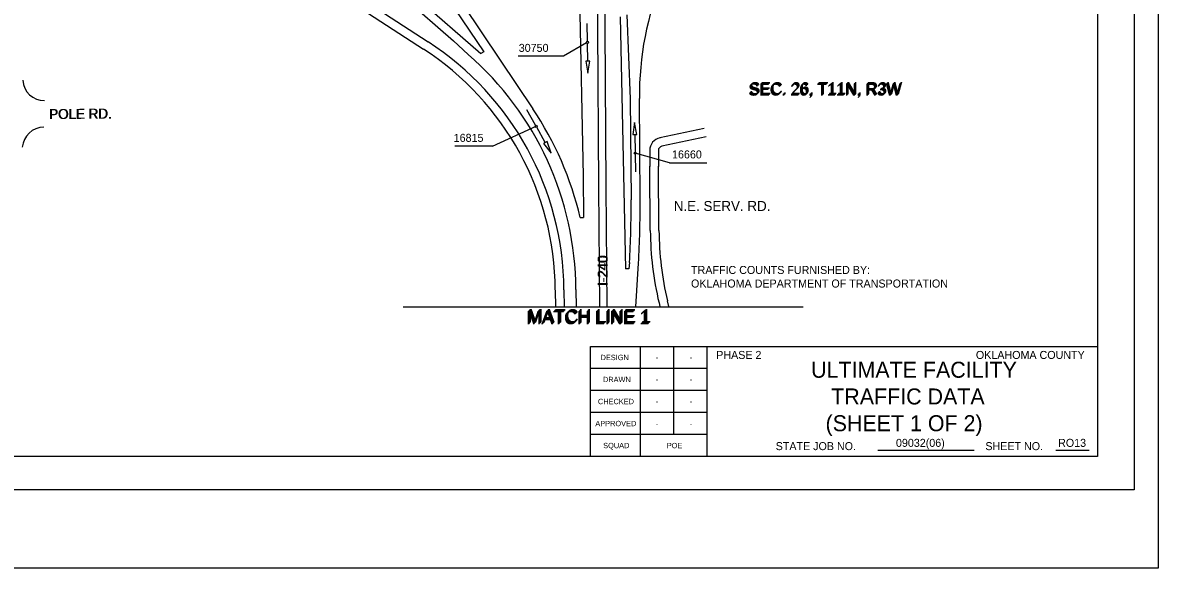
# Model space of a CAD drawing. Extents: x 137200 to 144400, y -2153713 to -2148447.
# Drawn here: x 140995 to 144400, y -2153247 to -2151611 of the extents above; entities that cross this region are included whole.
import ezdxf

# ---------------------------------------------------------------- set-up
doc = ezdxf.new("R2010")
doc.units = 0
for name, color, linetype in [('5', 7, 'Continuous'), ('6', 7, 'Continuous'), ('BASELINE', 7, 'Continuous'), ('EXIST', 7, 'Continuous'), ('PROP', 7, 'Continuous'), ('SHT_Plot_Shape_Full', 7, 'Continuous'), ('SHT_Plot_Shape_Half', 7, 'Continuous'), ('SHT_Sheet_Border', 7, 'Continuous'), ('SHT_Standard_Sheet_Lines', 7, 'Continuous'), ('SHT_Standard_Sheet_Txt', 7, 'Continuous'), ('T', 7, 'Continuous')]:
    doc.layers.add(name, color=color, linetype=linetype)

# ---------------------------------------------------------------- blocks, each defined once
blk = doc.blocks.new('ARR')
at = {"layer": '6'}
for p, q in [((134.5, 0), (0, 0)), ((285.8, 0), (151.3, 0))]:
    blk.add_line(p, q, dxfattribs=at)
blk.add_lwpolyline([(285.8, 15.2), (285.8, -15.2), (377.2, 0)], close=True, dxfattribs=at)
blk.add_circle((142.9, 0), 8.42, dxfattribs=at)

msp = doc.modelspace()

# ---------------------------------------------------------------- linework, layer by layer
at = {"layer": '6'}
for p, q in [((142685.6, -2151671.7), (142616.2, -2151711.8)), ((142616.2, -2151711.8), (142480.4, -2151711.8)), ((142403.7, -2151981.5), (142534.6, -2151921.7)), ((142538.9, -2151900.8), (142538.9, -2151900.8)), ((142403.7, -2151981.5), (142290.5, -2151981.5)), ((142934.2, -2152031.1), (142831.6, -2152002.6)), ((142934.2, -2152031.1), (143046.3, -2152031.1))]:
    msp.add_line(p, q, dxfattribs=at)
at = {"layer": 'BASELINE'}
msp.add_line((142135.5, -2152463.5), (143335.5, -2152463.5), dxfattribs=at)
at = {"layer": 'EXIST'}
for p, q in [((142592.1, -2152413), (142592.5, -2152464.5)), ((142618.1, -2152412.4), (142618.5, -2152464.3))]:
    msp.add_line(p, q, dxfattribs=at)
at = {"layer": 'PROP'}
for p, q in [((142712.7, -2150825), (142718.5, -2151627.2)), ((142734.7, -2150824.8), (142740.5, -2151627)), ((141506.8, -2151241.9), (142196.9, -2151690.4)), ((141520.9, -2151220.1), (142211.1, -2151668.6)), ((142658.1, -2151252.9), (142675.7, -2152071.4)), ((141903.1, -2151296.6), (142368.3, -2151703.3)), ((142023.6, -2151435.2), (142287.2, -2151665.6)), ((142292, -2151571.9), (142377.4, -2151698.9)), ((142314.4, -2151556.9), (142426.6, -2151723.5)), ((142786.2, -2151593.5), (142802.5, -2152349.5)), ((142806.2, -2151587.9), (142817, -2151839.2)), ((142718.5, -2151627.2), (142721.9, -2152103.4)), ((142740.5, -2151627), (142743.9, -2152103.2)), ((142287.2, -2151665.6), (142331.1, -2151706.6)), ((142287.2, -2151665.6), (142331.1, -2151706.6)), ((142377.4, -2151698.9), (142368.3, -2151703.3)), ((142426.6, -2151723.5), (142524.6, -2151869.1)), ((142817, -2151839.2), (142819.2, -2152142.7)), ((142846.2, -2152142.5), (142844, -2151839)), ((142876.8, -2152234.5), (142875.4, -2152041.5)), ((142902.8, -2152234.3), (142901.4, -2152041)), ((142675.7, -2152071.4), (142676.5, -2152195.2)), ((142675.7, -2152071.4), (142676.5, -2152195.2)), ((142721.9, -2152103.4), (142724.5, -2152463.5)), ((142743.9, -2152103.2), (142746.5, -2152463.4)), ((142666.5, -2152195.3), (142676.5, -2152195.2)), ((142666.5, -2152195.3), (142676.5, -2152195.2)), ((142814.3, -2152330.3), (142812.5, -2152349.4)), ((142833.6, -2152462.8), (142841.3, -2152331.9)), ((142812.5, -2152349.4), (142802.5, -2152349.5)), ((142654.1, -2152411.3), (142654.5, -2152464)), ((142903, -2152451.1), (142905.6, -2152462.3)), ((142932.3, -2152462.1), (142928.3, -2152445.1))]:
    msp.add_line(p, q, dxfattribs=at)
for points in [[(143038.7, -2151928.1), (142905.9, -2151956.2)], [(143044, -2151953.6), (142911.3, -2151981.7)], [(142901.1, -2151994.3), (142901.5, -2152042)], [(142875.1, -2151994.5), (142875.5, -2152042.2)]]:
    msp.add_lwpolyline(points, dxfattribs=at)
for centre, radius, start, end in [((143790.9, -2151832.2), 946.9, 90.3443, 180.4098), ((141723.6, -2152418.6), 894.5, 0.4098, 56.9808), ((141723.6, -2152418.6), 868.5, 0.4098, 56.9808), ((141709.2, -2152418), 944.9, 0.4098, 48.8404), ((141709.2, -2152418), 944.9, 0.4098, 48.8404), ((141060.2, -2151779.7), 65, 183.6752, 270.4098), ((141709.2, -2152418), 982.9, 13.0971, 33.9499), ((141709.2, -2152418), 982.9, 13.0971, 33.9499), ((141059, -2151989.7), 65, 90.4098, 175.7019), ((142914, -2151994.2), 38.8, 101.9396, 180.4098), ((142914, -2151994.2), 12.8, 101.9396, 180.4098), ((139973.5, -2152163), 2845.8, 356.6303, 0.4098), ((139973.5, -2152163), 2872.8, 356.6303, 0.4098), ((143844.7, -2152227.6), 967.9, 180.4098, 193.35), ((143844.7, -2152227.6), 941.9, 180.4098, 193.35)]:
    msp.add_arc(centre, radius, start, end, dxfattribs=at)
at = {"layer": 'SHT_Plot_Shape_Full'}
msp.add_lwpolyline([(137199.8, -2148447.1), (144399.8, -2148447.1), (144399.8, -2153247.1), (137199.8, -2153247.1)], close=True, dxfattribs=at)
at = {"layer": 'SHT_Plot_Shape_Half'}
msp.add_lwpolyline([(137527.3, -2148612.1), (144327.3, -2148612.1), (144327.3, -2153012.1), (137527.3, -2153012.1)], close=True, dxfattribs=at)
at = {"layer": 'SHT_Sheet_Border'}
for p, q in [((142697.3, -2152582.1), (144217.3, -2152582)), ((142697.3, -2152912.1), (142697.3, -2152582.1)), ((143047.3, -2152912.1), (143047.3, -2152581.9))]:
    msp.add_line(p, q, dxfattribs=at)
msp.add_lwpolyline([(144217.3, -2152912.1), (137917.3, -2152912.1), (137917.3, -2148712.1), (144217.3, -2148712.1)], close=True, dxfattribs=at)
at = {"layer": 'SHT_Standard_Sheet_Lines'}
for p, q in [((142847.3, -2152912.1), (142847.3, -2152581.9)), ((142947.3, -2152846), (142947.3, -2152581.9)), ((143559.5, -2152892.8), (143847.5, -2152892.8)), ((144092.4, -2152892.8), (144192.9, -2152892.8))]:
    msp.add_line(p, q, dxfattribs=at)
for points in [[(143047.3, -2152648.1), (142697.3, -2152648.1)], [(143047.3, -2152714.1), (142697.3, -2152714.1)], [(143047.3, -2152780.1), (142697.3, -2152780.1)], [(143047.3, -2152846.1), (142697.3, -2152846.1)]]:
    msp.add_lwpolyline(points, dxfattribs=at)

# ---------------------------------------------------------------- block references
at = {"layer": '6'}
for p, xscale, yscale, rotation in [((142687.7, -2151613.8), 0.3937, 0.39370000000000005, -89.1979575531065), ((142507.2, -2151872.6), 0.3937000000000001, 0.39370000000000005, -60.78130935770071), ((142832.9, -2152058.8), 0.39370000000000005, 0.3937, 91.28919224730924)]:
    msp.add_blockref('ARR', p, dxfattribs=dict(at, xscale=xscale, yscale=yscale, rotation=rotation))

# ---------------------------------------------------------------- texts
at = {"layer": '5'}
for s, height, p in [('SEC. 26, T11N, R3W', 36, (143175, -2151825.4)), ('SEC. 26, T11N, R3W', 36, (143170.3, -2151830.1)), ('SEC. 26, T11N, R3W', 36, (143171.9, -2151828.5)), ('SEC. 26, T11N, R3W', 36, (143173.5, -2151826.9)), ('N.E. SERV. RD.', 30, (142947.2, -2152175.8))]:
    msp.add_text(s, height=height, dxfattribs=at).set_placement(p)
for s, rotation, p in [('POLE RD.', 0.5333, (141074, -2151900.4)), ('POLE RD.', 0.5333, (141076, -2151900.4)), ('I-240', 90, (142749.1, -2152399.5)), ('I-240', 90, (142749.1, -2152401.5))]:
    msp.add_text(s, height=30, rotation=rotation, dxfattribs=at).set_placement(p)
at = {"layer": 'SHT_Standard_Sheet_Txt'}
for s, height, p in [('DESIGN', 16, (142727.8, -2152623)), ('OKLAHOMA COUNTY', 24, (143853, -2152619.4)), ('-', 16, (142893.4, -2152623)), ('-', 16, (142995.1, -2152623)), ('ULTIMATE FACILITY', 48, (143359, -2152675.8)), ('DRAWN', 16, (142734.9, -2152689)), ('-', 16, (142893.4, -2152689)), ('-', 16, (142995.1, -2152689)), ('TRAFFIC DATA', 48, (143419.3, -2152755.9)), ('CHECKED', 16, (142719.9, -2152755)), ('-', 16, (142893.4, -2152755)), ('-', 16, (142995.1, -2152755)), ('APPROVED', 16, (142712.1, -2152821)), ('(SHEET 1 OF 2)', 48, (143402.3, -2152836.1)), ('-', 16, (142893.4, -2152821.1)), ('-', 16, (142995.1, -2152821.1)), ('SQUAD', 16, (142735.6, -2152887)), ('POE', 16, (142926.3, -2152887.1)), ('STATE JOB NO.', 24, (143252.8, -2152892.8)), ('09032(06)', 24, (143613.4, -2152883)), ('SHEET NO. ', 24, (143881.4, -2152892.8)), ('RO13', 24, (144099.5, -2152883))]:
    msp.add_text(s, height=height, dxfattribs=at).set_placement(p)
msp.add_text('PHASE 2', height=24, rotation=0, dxfattribs=at).set_placement((143074.5, -2152619.4))
at = {"layer": 'T'}
for s, height, p in [('30750', 24, (142482.5, -2151698.8)), ('16815', 24, (142287.4, -2151968.5)), ('16660', 24, (142942.1, -2152018.2)), ('TRAFFIC COUNTS FURNISHED BY:', 24, (142999, -2152364.6)), ('OKLAHOMA DEPARTMENT OF TRANSPORTATION', 24, (142999, -2152405.3)), ('MATCH LINE 1', 40, (142510.6, -2152510)), ('MATCH LINE 1', 40, (142505.1, -2152515.5)), ('MATCH LINE 1', 40, (142506.9, -2152513.7)), ('MATCH LINE 1', 40, (142508.7, -2152511.8))]:
    msp.add_text(s, height=height, dxfattribs=at).set_placement(p)

doc.saveas('drawing.dxf')
